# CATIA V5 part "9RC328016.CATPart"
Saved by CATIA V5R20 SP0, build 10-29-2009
Part number: 9RC328016
Revision: ANY
Definition: UNKNOWN
Nomenclature: 9RC328016
Source: Unknown
Bounding box of the stored display mesh (mm): x -64.6 to 16, y -16 to 16, z -7.85 to 7.85
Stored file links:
  C:\Users\Utente\Desktop\IO LAVORO\3D X SITO CF\CUMSA\3D files RC\RC 328016\9RC328016.CATPart
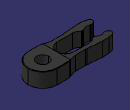
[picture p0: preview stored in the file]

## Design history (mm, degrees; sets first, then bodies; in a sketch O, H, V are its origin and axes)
Body1 "Chaflán1" (main body)
  Solid1: solid without history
